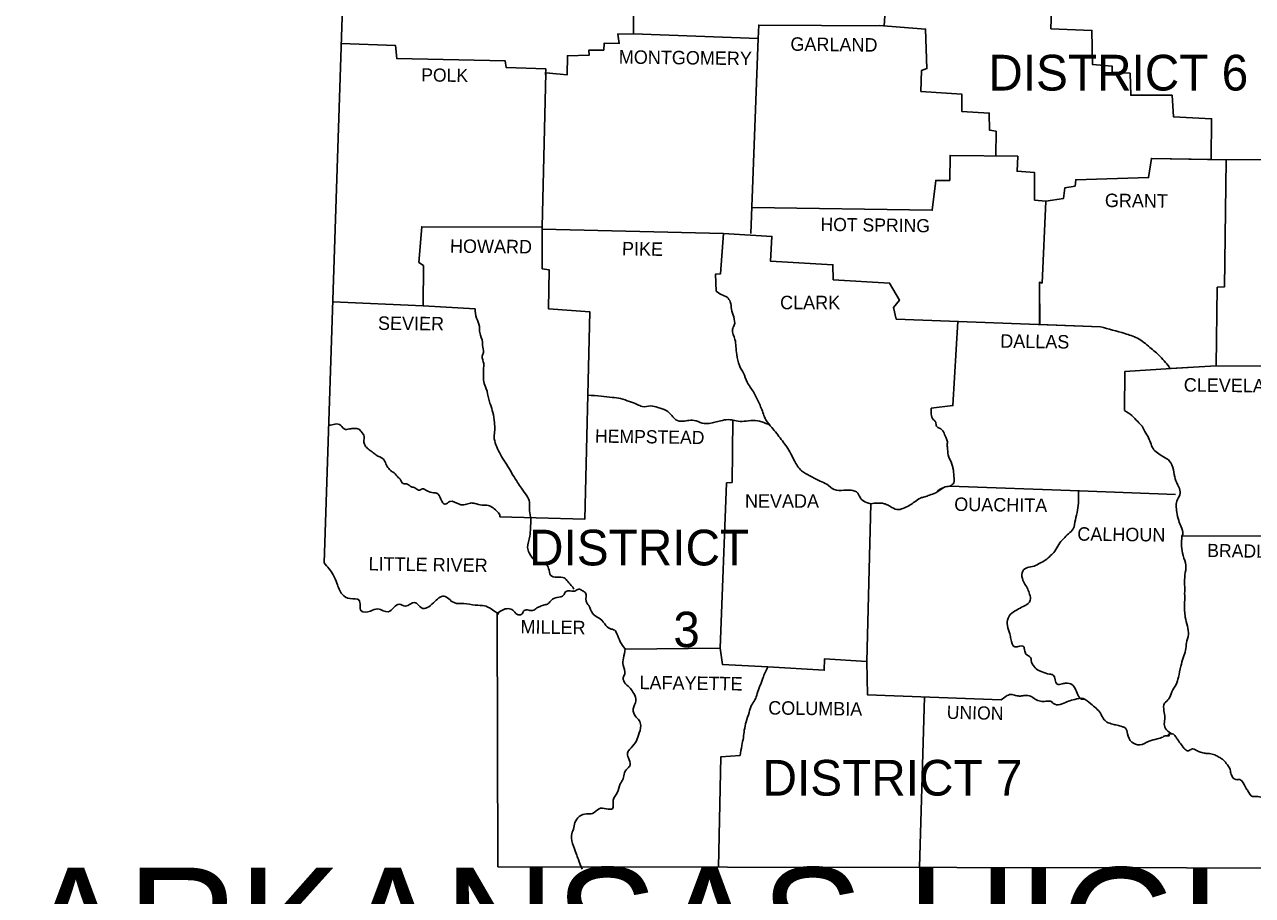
# Model space of a CAD drawing. Extents: x 3046 to 131673, y -8885 to 10756.
# Drawn here: x 24945 to 28781, y 4994 to 7714 of the extents above; entities that cross this region are included whole.
import ezdxf

# ---------------------------------------------------------------- set-up
doc = ezdxf.new("R2010")
doc.units = 0
for name, color, linetype in [('1', 7, 'Continuous'), ('2', 7, 'Continuous'), ('3', 7, 'Continuous'), ('R_Annotation', 7, 'Continuous')]:
    doc.layers.add(name, color=color, linetype=linetype)

msp = doc.modelspace()

# ---------------------------------------------------------------- linework, layer by layer
at = {"layer": '1'}
for points in [[(25766.1, 10313), (25968.7, 8686.9), (25880.6, 6032.5)], [(26849.2, 8257.4), (26847.3, 7685), (26798.3, 7684), (26802.3, 7654.7), (26755.3, 7655.6), (26754.3, 7634.1), (26708.3, 7634.1), (26709.3, 7618.5), (26640.8, 7616.5), (26639.8, 7556.8), (26573.3, 7562.7), (26562.5, 7081.3), (26185.9, 7082.3), (26177.1, 6970.8), (26190.8, 6961), (26189.8, 6835.7), (25907.7, 6848.1)], [(27958.7, 7826.9), (27638.8, 7836.6), (27630, 7710.4), (27238.6, 7712.4), (27236.7, 7670.3)], [(28039, 7830.2), (28155.4, 7822.9), (28151.5, 7700.6), (28279.7, 7695.8), (28281.6, 7589.1), (28342.3, 7584.2), (28342.3, 7565.6), (28399, 7561.7), (28401, 7493.2), (28530.1, 7493.2), (28534, 7425.7), (28653.4, 7419.8), (28652.4, 7292.5)], [(27236.7, 7670.3), (26847.3, 7685)], [(27614.4, 7710.5), (27760.1, 7699.7), (27764, 7576.4), (27747.4, 7570.5), (27745.4, 7505), (27873.6, 7496.2), (27873.6, 7442.3), (27958.7, 7437.5), (27959.7, 7383.6), (27980.3, 7380.7), (27979.2, 7303.4)], [(25934.4, 7654.7), (26103.7, 7648.8), (26107.6, 7607.7), (26446.1, 7600.8), (26450, 7579.3), (26573.3, 7575.4), (26572.3, 7556.8)], [(27236.7, 7670.3), (27214.2, 7060.8)], [(29819.7, 7405.2), (29449.8, 7414.9), (29447.9, 7294.6), (28699.4, 7291.7)], [(27217.2, 7142), (27780.7, 7134.1), (27791.4, 7227.1), (27835.5, 7227.1), (27836.4, 7305.4), (28047.8, 7302.4), (28045.8, 7255.5), (28100.6, 7251.6), (28100.6, 7165.5), (28135.8, 7162.5)], [(28135.8, 7162.5), (28190.6, 7170.3), (28194.5, 7203.6), (28226.8, 7209.5), (28228.8, 7229), (28456.7, 7235.9), (28465.5, 7295.6), (28699.4, 7291.7)], [(28699.4, 7289.7), (28693.5, 6894.4), (28671, 6893.5), (28668.1, 6647.9)], [(28135.8, 7162.5), (28124.1, 6906.2), (28115.3, 6909.1), (28116.3, 6776)], [(26562.5, 7081.3), (26562.5, 6951.2), (26584.1, 6947.3), (26582.1, 6825.9), (26711.3, 6816.2), (26695.6, 6169.4), (26429.5, 6176.3)], [(26562.5, 7074.5), (27129, 7061.7)], [(27105.6, 6880.7), (27103.6, 6934.5), (27119.3, 6935.5), (27129, 7061.7), (27279.7, 7052), (27275.8, 6974.7), (27470.5, 6963.9), (27471.5, 6916.9), (27647.6, 6906.2), (27677.9, 6853.3), (27659.3, 6829.9), (27668.1, 6793.7), (28306.1, 6770.2)], [(26189.8, 6835.7), (26352.2, 6825.9)], [(27860.6, 6786.6), (27845.2, 6523.6), (27777.7, 6515.8)], [(28527.2, 6639.1), (28382.4, 6630.3), (28381.4, 6508)], [(28668.1, 6647.9), (28525.2, 6639.1)], [(28668.1, 6647.9), (29016.4, 6645.9)], [(27157.4, 6478.6), (27155.5, 6283.9), (27137.9, 6282), (27118.3, 5766.3)], [(27835.5, 6272.2), (28240.5, 6257.5), (28540.9, 6245.8)], [(27588.9, 6217.4), (27576.2, 5724.3), (27444.1, 5733.1), (27443.1, 5696.9), (27267, 5707.6)], [(28560.5, 6115.6), (29002.7, 6116.6)], [(26421.7, 5874.9), (26423.6, 5083.4), (30009.5, 5077.5)], [(27267, 5707.6), (27125.1, 5715.5), (27118.3, 5766.3), (26821.8, 5763.4)], [(27995.9, 5604.9), (27578.1, 5620.5), (27576.1, 5724.3)], [(27756.3, 5613.9), (27740.7, 5081.2)], [(27180.9, 5430.7), (27120.2, 5426.8), (27113.4, 5082.4)]]:
    msp.add_lwpolyline(points, dxfattribs=at)
for points in [[(27105.6, 6880.7), (27121.2, 6871), (27139.8, 6862.1), (27149.6, 6847.5), (27153.5, 6825), (27160.4, 6800.5), (27162.3, 6775.1), (27156.4, 6761.4), (27164.3, 6730.1), (27167.2, 6708.5), (27170.1, 6683.1), (27178, 6648.9), (27190.7, 6625.4), (27202.4, 6597), (27222, 6566.7), (27238.6, 6533.4), (27246.5, 6515.8), (27261.1, 6479.6), (27279.7, 6455.1), (27309.1, 6418), (27335.5, 6379.8), (27350.2, 6351.4), (27372.7, 6320.1), (27398.1, 6304.5), (27430.4, 6287.8), (27450.9, 6278), (27474.4, 6261.4), (27504.8, 6259.4), (27527.3, 6259.4), (27547.8, 6250.6), (27557.6, 6233), (27575.2, 6221.3), (27588.9, 6217.4)], [(26352.2, 6825.9), (26357.1, 6796.6), (26365.9, 6771.2), (26366.9, 6751.6), (26375.7, 6722.2), (26375.7, 6711.5), (26378.6, 6689.9), (26374.7, 6678.2), (26379.6, 6654.7), (26378.6, 6637.1), (26378.6, 6622.4), (26379.6, 6598), (26387.4, 6576.5), (26395.2, 6544.2), (26400.1, 6527.5), (26408, 6502.1), (26412.9, 6470.8), (26413.8, 6447.3), (26411.9, 6425.8), (26417.7, 6401.3), (26428.5, 6376.9), (26442.2, 6353.4), (26458.8, 6327), (26470.6, 6306.4), (26485.3, 6283.9), (26497, 6265.3), (26514.6, 6241.8), (26522.4, 6222.3), (26522.4, 6194.9), (26526.3, 6169.4), (26525.4, 6141.1), (26523.4, 6115.6), (26516.6, 6080.4), (26521.5, 6063.8), (26540, 6039.3), (26551.8, 6032.5), (26572.3, 6028.5), (26582.1, 6014.8), (26588, 5994.3), (26608.5, 5987.5), (26631, 5985.5), (26641.8, 5973.8), (26656.5, 5958.1), (26661.4, 5950.3)], [(28306.1, 6770.2), (28382.4, 6748.7), (28421.5, 6734), (28460.7, 6705.6), (28492.9, 6677.2), (28525.2, 6639.1)], [(26705, 6556.2), (26746.5, 6553), (26780.7, 6549.1), (26807.1, 6546.1), (26834.5, 6536.3), (26859, 6527.5), (26874.7, 6520.7), (26901.1, 6522.6), (26923.6, 6517.7), (26949, 6508.9), (26967.6, 6492.3), (26979.3, 6479.6), (27001.9, 6474.7), (27020.4, 6477.6), (27042.9, 6475.7), (27068.4, 6467.8), (27088.9, 6468.8), (27105.6, 6472.7), (27125.1, 6477.6), (27149.6, 6479.6), (27168.2, 6475.7), (27192.6, 6474.7), (27221, 6477.6), (27274.3, 6462.8)], [(27777.7, 6515.8), (27777.7, 6497.2), (27784.6, 6479.6), (27791.4, 6471.8), (27794.4, 6459), (27803.2, 6453.2), (27815.9, 6441.4), (27822.7, 6424.8), (27827.6, 6414), (27827.6, 6400.3), (27828.6, 6386.6), (27830.6, 6370), (27842.3, 6340.7), (27845.2, 6328.9), (27847.2, 6319.1), (27848.2, 6302.5), (27848.2, 6282.9), (27835.5, 6272.2)], [(28381.4, 6508), (28403.9, 6493.3), (28422.5, 6473.7), (28436.2, 6459), (28445, 6442.4), (28456.7, 6422.8), (28473.4, 6385.7), (28488.1, 6372.9), (28508.6, 6360.2), (28521.3, 6351.4), (28534, 6323), (28539.9, 6294.7), (28550.7, 6269.2), (28555.6, 6249.7), (28546.8, 6230.1), (28544.8, 6191), (28550.7, 6164.5), (28558.5, 6145), (28563.4, 6122.5), (28560.5, 6115.6)], [(25894.5, 6460.3), (25932.5, 6462), (25947.1, 6449.3), (25955.9, 6450.2), (25971.6, 6452.2), (25986.3, 6451.2), (25997, 6442.4), (26005.8, 6426.8), (26004.9, 6412.1), (26005.8, 6406.2), (26012.7, 6393.5), (26024.4, 6383.7), (26037.1, 6373.9), (26048.9, 6366.1), (26068.5, 6353.4), (26070.4, 6349.5), (26078.2, 6333.8), (26088, 6321.1), (26099.8, 6313.3), (26112.5, 6299.6), (26118.4, 6293.7), (26128.1, 6280), (26138.9, 6279), (26153.6, 6270.2), (26164.3, 6267.3), (26176.1, 6259.4), (26187.8, 6263.4), (26202.5, 6257.5), (26222.1, 6251.6), (26232.8, 6249.7), (26245.5, 6231.1), (26258.3, 6215.4), (26273.9, 6224.2), (26303.3, 6215.4), (26321.9, 6214.4), (26338.5, 6219.3), (26351.2, 6218.4), (26374.7, 6212.5), (26389.4, 6212.5), (26405, 6206.6), (26419.7, 6194.9), (26429.5, 6182.2), (26429.5, 6176.3)], [(27816.9, 6268.3), (27791.4, 6251.6), (27771.9, 6243.8), (27757.2, 6238.9), (27743.5, 6235), (27725.9, 6223.2), (27712.2, 6213.5), (27693.6, 6204.7), (27676, 6198.8), (27654.5, 6205.6), (27642.7, 6212.5), (27630, 6217.4), (27588.9, 6217.4)], [(27791.4, 6251.6), (27816.9, 6268.3), (27835.5, 6272.2)], [(28237.1, 6257.8), (28234.6, 6196.8), (28227.8, 6166.5), (28220.9, 6139.1), (28206.3, 6123.5), (28190.6, 6107.8), (28175.9, 6090.2), (28163.2, 6068.7), (28150.5, 6055), (28133.9, 6041.3), (28117.2, 6031.5), (28098.6, 6022.7), (28078.1, 6017.8), (28063.4, 6007), (28062.4, 5983.5), (28079.1, 5950.3), (28084.9, 5934.6), (28086.9, 5916), (28080.1, 5905.3), (28064.4, 5896.5), (28045.8, 5885.7), (28029.2, 5875.9), (28017.4, 5859.3), (28015.5, 5836.8), (28023.3, 5810.4), (28026.2, 5794.7), (28039, 5770.2), (28048.7, 5771.2), (28066.4, 5770.2), (28068.3, 5765.4), (28069.3, 5760.5), (28073.2, 5747.7), (28087.9, 5737), (28089.8, 5727.2), (28098.6, 5708.6), (28113.3, 5695.9), (28124.1, 5692), (28146.6, 5685.1), (28158.3, 5682.2), (28171, 5653.8), (28186.7, 5654.8), (28198.4, 5656.8), (28218, 5651.9), (28226.8, 5640.1), (28235.6, 5620.5), (28247.4, 5606.9), (28255.2, 5606.9)], [(28560.5, 6115.6), (28564.4, 6055), (28573.2, 6025.6), (28570.2, 5994.3), (28569.3, 5964), (28569.3, 5936.6), (28569.3, 5910.2), (28569.3, 5882.8), (28571.2, 5863.2), (28578.1, 5834.8), (28581, 5808.4), (28575.1, 5783), (28572.2, 5759.5), (28564.4, 5736), (28557.5, 5709.6), (28549.7, 5675.3), (28542.8, 5652.8), (28529.1, 5629.4), (28520.3, 5607.8), (28506.6, 5594.1), (28504.7, 5570.7), (28507.6, 5549.1), (28505.7, 5529.6), (28512.5, 5511), (28530.1, 5498.2)], [(25880.6, 6032.5), (25909, 5995.3), (25920.7, 5968.9), (25937.3, 5934.6), (25961.8, 5920.9), (25990.2, 5916), (25996.1, 5882.8), (26025.4, 5881.8), (26048.9, 5888.6), (26081.2, 5879.8), (26115.4, 5903.3), (26135, 5897.4), (26163.4, 5909.2), (26184.9, 5891.6), (26222.1, 5907.2), (26255.3, 5928.7), (26286.6, 5908.2), (26317, 5905.3), (26353.2, 5900.4), (26381.5, 5898.4), (26407, 5885.7), (26425.6, 5873), (26421.7, 5874.9)], [(26421.7, 5874.9), (26455.9, 5889.6), (26470.6, 5884.7), (26483.3, 5872), (26498, 5872), (26505.8, 5883.7), (26520.5, 5884.7), (26532.2, 5883.7), (26544.9, 5891.6), (26555.7, 5896.5), (26570.4, 5901.4), (26581.1, 5905.3), (26590.9, 5916), (26608.5, 5924.8), (26629.1, 5931.7), (26635, 5941.5), (26644.7, 5945.4), (26664.3, 5944.4), (26677, 5950.3), (26687.8, 5945.4), (26697.6, 5938.5), (26699.5, 5913.1), (26707.4, 5899.4), (26719.1, 5874.9), (26735.7, 5862.2), (26751.4, 5849.5), (26757.3, 5841.7), (26773.9, 5827), (26788.6, 5822.1), (26795.4, 5811.3), (26806.2, 5785.9), (26821.8, 5763.4)], [(26821.8, 5763.4), (26816, 5735), (26815, 5712.5), (26819.9, 5686.1), (26815, 5673.4), (26822.8, 5654.8), (26837.5, 5640.1), (26848.2, 5624.5), (26855.1, 5602), (26846.3, 5576.5), (26856.1, 5550.1), (26864.9, 5540.3), (26869.8, 5524.7), (26862.9, 5494.3), (26854.1, 5471.8), (26834.5, 5449.3), (26828.7, 5438.6), (26831.6, 5423.9), (26836.5, 5400.4), (26831.6, 5393.6), (26818.9, 5376.9), (26815, 5358.3), (26806.2, 5342.7), (26796.4, 5314.3), (26783.7, 5290.8), (26781.7, 5264.4), (26762.1, 5264.4), (26739.6, 5264.4), (26719.1, 5249.7), (26700.5, 5248.8), (26678, 5239.9), (26664.3, 5221.4), (26659.4, 5200.8), (26653.5, 5181.2), (26659.4, 5148), (26668.2, 5124.5), (26675.1, 5105.9), (26686.8, 5075.6)], [(27180.9, 5430.7), (27185.8, 5462), (27190.7, 5486.5), (27193.6, 5510), (27199.5, 5536.4), (27208.3, 5564.8), (27216.1, 5588.3), (27226.9, 5604.9), (27233.7, 5624.5), (27242.5, 5647.9), (27251.3, 5672.4), (27267, 5707.6)], [(27995.9, 5604.9), (28011.6, 5615.7), (28026.2, 5621.5), (28040.9, 5618.6), (28056.6, 5616.6), (28070.3, 5618.6), (28087.9, 5615.7), (28102.6, 5606.9), (28119.2, 5600), (28135.8, 5600), (28150.5, 5600), (28163.2, 5591.2), (28186.7, 5592.2), (28206.3, 5600), (28225.8, 5605.9), (28252.3, 5608.8), (28275.7, 5592.2), (28292.4, 5578.5), (28306.1, 5562.8), (28315.9, 5545.2), (28326.6, 5535.4), (28344.2, 5528.6), (28357.9, 5525.6), (28374.6, 5520.8), (28383.4, 5516.8), (28391.2, 5498.2), (28403.9, 5472.8), (28428.4, 5464), (28458.7, 5475.7), (28483.2, 5482.6), (28500.8, 5488.5), (28511.5, 5492.4), (28521.3, 5493.4), (28518.4, 5495.3), (28530.1, 5498.2), (28540.9, 5490.4), (28547.7, 5479.7), (28559.5, 5464), (28570.2, 5450.3), (28581, 5445.4), (28591.8, 5451.3), (28606.4, 5446.4), (28619.2, 5441.5), (28633.8, 5437.6), (28646.6, 5436.6), (28663.2, 5432.7), (28675.9, 5425.8), (28687.6, 5419), (28699.4, 5406.3), (28711.1, 5386.7), (28715, 5371.1), (28728.7, 5355.4), (28741.5, 5355.4), (28760, 5330), (28766.9, 5320.2), (28781.6, 5302.6), (28792.3, 5302.6), (28812.9, 5298.7)]]:
    msp.add_spline(points, degree=3, dxfattribs=at)
at = {"layer": 'R_Annotation'}
for p, q in [((28116.2, 6777.2), (28306.1, 6770.2)), ((28668.1, 6647.9), (29016.4, 6645.9))]:
    msp.add_line(p, q, dxfattribs=at)
for points in [[(28699.4, 7291.7), (28652.4, 7292.5), (28465.5, 7295.6), (28456.7, 7235.9), (28228.8, 7229), (28226.8, 7209.5), (28194.5, 7203.6), (28190.6, 7170.3), (28135.8, 7162.5)], [(29319.8, 7294.1), (28915.6, 7292.5), (28699.4, 7291.7)], [(28135.8, 7162.5), (28124.1, 6906.2), (28115.3, 6909.1), (28116.2, 6777.2)], [(28525.2, 6639.1), (28527.2, 6639.2), (28668.1, 6647.9)]]:
    msp.add_lwpolyline(points, dxfattribs=at)
msp.add_spline([(28306.1, 6770.2), (28382.4, 6748.7), (28421.5, 6734), (28460.7, 6705.6), (28492.9, 6677.2), (28525.2, 6639.1)], degree=3, dxfattribs=at)

# ---------------------------------------------------------------- texts
at = {"layer": '2'}
for s, height, rotation, p in [('GARLAND', 42.07, 359.3658, (27337.4, 7632.2)), ('MONTGOMERY', 42.07, 359.2944, (26801.3, 7592)), ('POLK', 41.08, 359.2152, (26183.9, 7536.3)), ('GRANT', 42.07, 359.4032, (28319.8, 7143.9)), ('HOT SPRING', 41.09, 359.2216, (27431.4, 7069.6)), ('HOWARD', 42.07, 359.5145, (26273.9, 7001.1)), ('PIKE', 42.06, 359.0452, (26811.1, 6993.3)), ('SEVIER', 42.07, 359.4271, (26048.9, 6760.4)), ('DALLAS', 42.06, 359.2462, (27993, 6704.6)), ('CLEVELAND', 42.07, 359.3377, (28566.3, 6567.6)), ('HEMPSTEAD', 41.08, 359.1885, (26726.9, 6408.2)), ('OUACHITA', 42.07, 359.2043, (27849.2, 6194.9)), ('CALHOUN', 42.07, 359.3634, (28233.7, 6101.9)), ('BRADLEY', 41.08, 359.1449, (28639.7, 6051)), ('LITTLE RIVER', 42.073, 359.1697, (26019.5, 6009)), ('MILLER', 42.06, 359.1319, (26494.1, 5812.3)), ('LAFAYETTE', 42.06, 359.1839, (26865.9, 5638.2)), ('COLUMBIA', 42.06, 359.2125, (27268, 5558.9)), ('UNION', 41.09, 358.9584, (27825.7, 5545.2))]:
    msp.add_text(s, height=height, rotation=rotation, dxfattribs=at).set_placement(p)
for s, height, p in [('CLARK', 42.07, (27305.3, 6824.7)), ('NEVADA', 42.07, (27195.6, 6204.7)), ('ARKANSAS HIGHWAY DISTRICT 2', 360, (24943.9, 4720.5))]:
    msp.add_text(s, height=height, dxfattribs=at).set_placement(p)
at = {"layer": '3'}
for s, height, p in [('DISTRICT 6', 111.54, (27955.8, 7507.9)), ('DISTRICT', 111.54, (26521, 6024.5)), ('3', 110.6, (26972, 5769.2)), ('DISTRICT 7', 111.54, (27250.4, 5305.5))]:
    msp.add_text(s, height=height, dxfattribs=at).set_placement(p)

doc.saveas('drawing.dxf')
